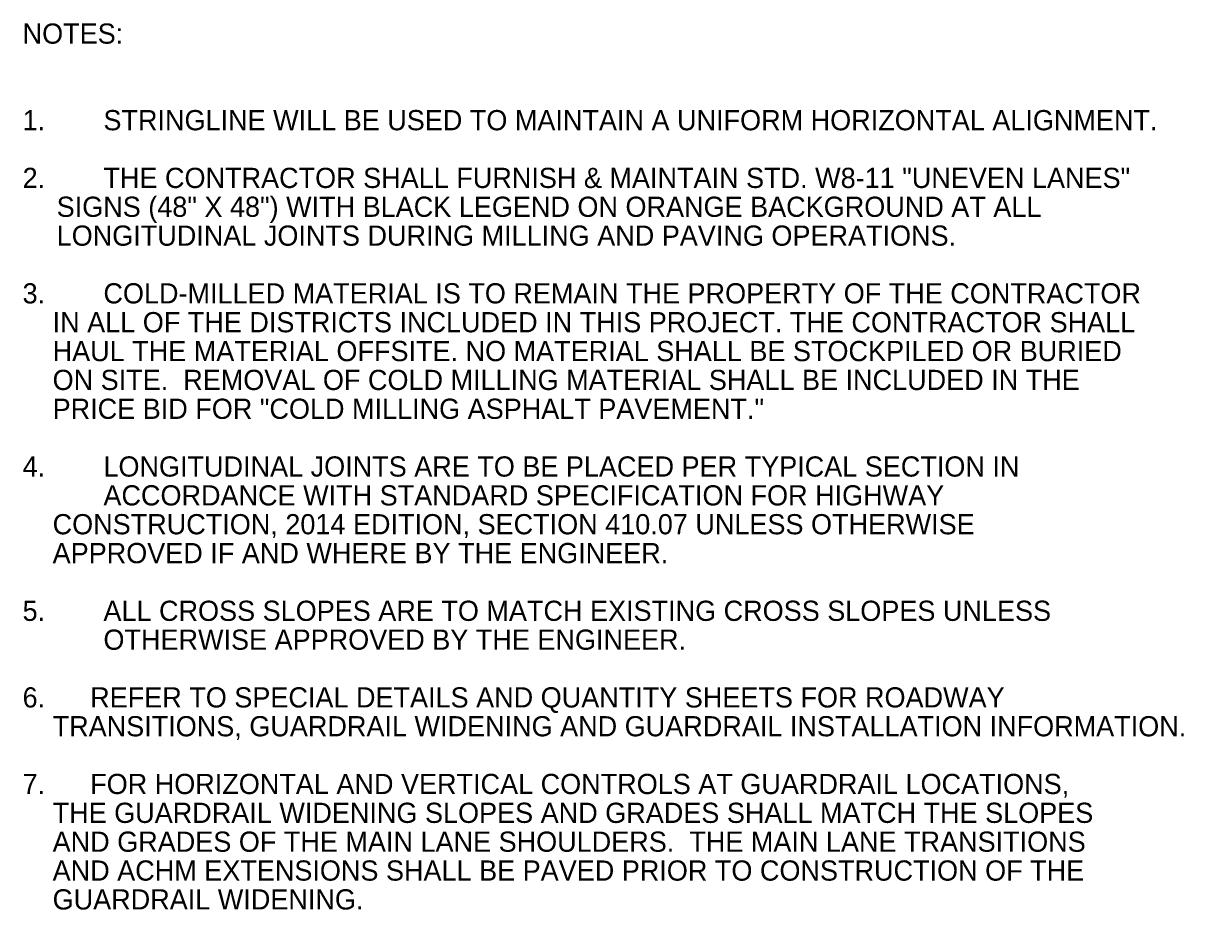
# Model space of a CAD drawing. Extents: x 544199 to 1930787, y -1968972 to 596640.
# Drawn here: x 550902.6 to 551304.6, y -1957257 to -1956949.8 of the extents above; entities that cross this region are included whole.
import ezdxf

# ---------------------------------------------------------------- set-up
doc = ezdxf.new("R2010")
doc.units = 0
doc.layers.add('R_Border Notes', color=7, linetype='Continuous')

msp = doc.modelspace()

# ---------------------------------------------------------------- texts
at = {"layer": 'R_Border Notes'}
for s, p in [('NOTES: ', (550902.36, -1956956.88)), ('1.', (550902.36, -1956986.88)), ('STRINGLINE WILL BE USED TO MAINTAIN A UNIFORM HORIZONTAL ALIGNMENT.', (550930.36, -1956986.88)), ('2.', (550902.36, -1957006.88)), ('THE CONTRACTOR SHALL FURNISH & MAINTAIN STD. W8-11 "UNEVEN LANES" ', (550930.36, -1957006.88)), ('    SIGNS (48" X 48") WITH BLACK LEGEND ON ORANGE BACKGROUND AT ALL ', (550903.76, -1957016.88)), ('    LONGITUDINAL JOINTS DURING MILLING AND PAVING OPERATIONS.', (550903.76, -1957026.88)), ('3.', (550902.36, -1957046.88)), ('COLD-MILLED MATERIAL IS TO REMAIN THE PROPERTY OF THE CONTRACTOR', (550930.36, -1957046.88)), ('    IN ALL OF THE DISTRICTS INCLUDED IN THIS PROJECT. THE CONTRACTOR SHALL', (550902.36, -1957056.88)), ('    HAUL THE MATERIAL OFFSITE. NO MATERIAL SHALL BE STOCKPILED OR BURIED', (550902.36, -1957066.88)), ('    ON SITE.  REMOVAL OF COLD MILLING MATERIAL SHALL BE INCLUDED IN THE', (550902.36, -1957076.88)), ('    PRICE BID FOR "COLD MILLING ASPHALT PAVEMENT."', (550902.36, -1957086.88)), ('4.', (550902.36, -1957106.88)), ('LONGITUDINAL JOINTS ARE TO BE PLACED PER TYPICAL SECTION IN ', (550930.36, -1957106.88)), ('ACCORDANCE WITH STANDARD SPECIFICATION FOR HIGHWAY', (550930.36, -1957116.88)), ('    CONSTRUCTION, 2014 EDITION, SECTION 410.07 UNLESS OTHERWISE', (550902.36, -1957126.88)), ('    APPROVED IF AND WHERE BY THE ENGINEER.', (550902.36, -1957136.88)), ('5.', (550902.36, -1957156.88)), ('ALL CROSS SLOPES ARE TO MATCH EXISTING CROSS SLOPES UNLESS ', (550930.36, -1957156.88)), ('OTHERWISE APPROVED BY THE ENGINEER.', (550930.36, -1957166.88)), ('6.      REFER TO SPECIAL DETAILS AND QUANTITY SHEETS FOR ROADWAY', (550902.36, -1957186.88)), ('    TRANSITIONS, GUARDRAIL WIDENING AND GUARDRAIL INSTALLATION INFORMATION.', (550902.36, -1957196.88)), ('7.      FOR HORIZONTAL AND VERTICAL CONTROLS AT GUARDRAIL LOCATIONS,', (550902.36, -1957216.88)), ('    THE GUARDRAIL WIDENING SLOPES AND GRADES SHALL MATCH THE SLOPES', (550902.36, -1957226.88)), ('    AND GRADES OF THE MAIN LANE SHOULDERS.  THE MAIN LANE TRANSITIONS', (550902.36, -1957236.88)), ('    AND ACHM EXTENSIONS SHALL BE PAVED PRIOR TO CONSTRUCTION OF THE', (550902.36, -1957246.88)), ('    GUARDRAIL WIDENING.', (550902.36, -1957256.88))]:
    msp.add_text(s, height=7, dxfattribs=at).set_placement(p)

doc.saveas('drawing.dxf')
